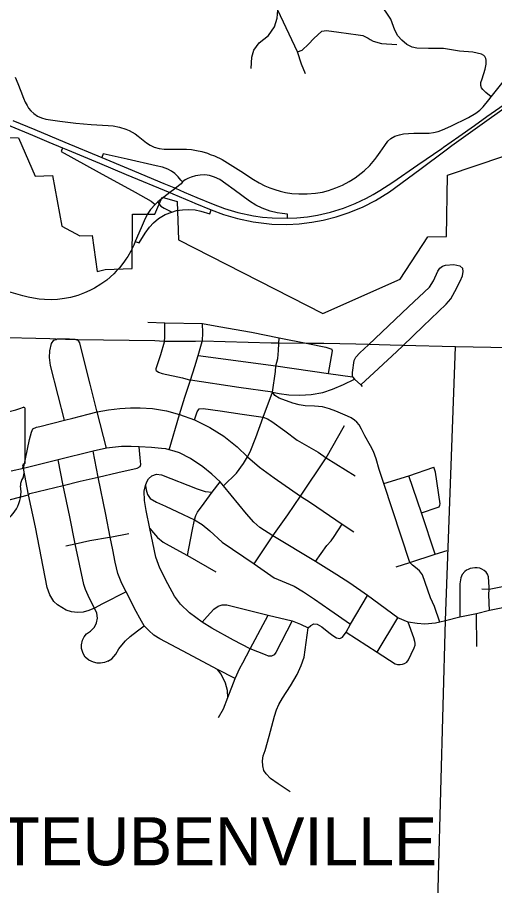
# Model space of a CAD drawing. Extents: x 2402298 to 2498138, y 789485 to 950881.
# Drawn here: x 2482051 to 2487007, y 865555 to 874577 of the extents above; entities that cross this region are included whole.
import ezdxf

# ---------------------------------------------------------------- set-up
doc = ezdxf.new("R2010")
doc.units = 0
for name, color, linetype in [('GM_X_City_Street', 7, 'Continuous'), ('GM_X_Corporation', 7, 'Continuous'), ('GM_X_Corporation_Text', 7, 'Continuous'), ('GM_X_County_Road', 7, 'Continuous'), ('GM_X_Interchange_Ramps', 7, 'Continuous'), ('GM_X_State_Route', 7, 'Continuous'), ('GM_X_State_Shield', 7, 'Continuous'), ('GM_X_Township', 7, 'Continuous'), ('GM_X_Township_Road', 7, 'Continuous'), ('GM_X_US_Route', 7, 'Continuous')]:
    doc.layers.add(name, color=color, linetype=linetype)

msp = doc.modelspace()

# ---------------------------------------------------------------- linework, layer by layer
at = {"layer": 'GM_X_City_Street'}
for p, q in [((2485259, 870000.6), (2485448.7, 870337.6)), ((2485785.7, 867979.3), (2486002.2, 868338)), ((2486821.1, 868038.8), (2486820, 868379.3))]:
    msp.add_line(p, q, dxfattribs=at)
for points in [[(2485529.5, 870840.6), (2485532.2, 870887.3), (2485548.1, 871011.7), (2485564.1, 871047.4), (2485608.8, 871091.4), (2485695.9, 871174), (2486111.1, 871567.8), (2486331.8, 871773.4), (2486373.6, 871839.4), (2486417.6, 871938), (2486437.3, 871972.2), (2486465.4, 871990), (2486498, 872000.2), (2486583.7, 872007.1), (2486647.5, 871994.9)], [(2485619.1, 870757.2), (2485801.5, 870928.6), (2485990.1, 871105), (2486052.9, 871165.3), (2486265.5, 871369), (2486503.7, 871596.6), (2486552.2, 871650.5), (2486594.7, 871728.7), (2486647.8, 871837.1), (2486672.9, 871892.5), (2486682, 871937.3), (2486677.4, 871968.4), (2486647.5, 871994.9)], [(2483406.8, 871408.5), (2483583.9, 871402.8), (2483973.6, 871397)], [(2483490.8, 870908.7), (2483492.5, 870926.9), (2483539.3, 871074.1), (2483577.9, 871205.5), (2483583.2, 871256.4), (2483583.9, 871402.8)], [(2483628.1, 870081.7), (2483736.2, 870449.4), (2483791.5, 870630.9), (2483849.8, 870805.7), (2483892.5, 870949.3), (2483929.2, 871064.9), (2483970.6, 871209.8), (2483972.4, 871216.1), (2483975.4, 871300.2), (2483973.6, 871397)], [(2483973.6, 871397), (2484143.6, 871365.7), (2484483.7, 871305.6), (2484769.1, 871246.2), (2485068.2, 871186.5), (2485254, 871149.4), (2485315.3, 871127.8)], [(2482541.1, 870391.7), (2482473.8, 870646.5), (2482395.7, 870957.8), (2482383.7, 871043.1), (2482387.9, 871112.8), (2482406.5, 871189.1), (2482430.6, 871222.7), (2482452.7, 871231), (2482466, 871235.9), (2482592.4, 871236.4), (2482648.7, 871232.9), (2482678.7, 871224), (2482682.9, 871222.7)], [(2482876.3, 870488.8), (2482806.7, 870766.1), (2482748.4, 870996.2), (2482698.6, 871193.9), (2482682.9, 871222.7)], [(2484190.9, 869709.4), (2484326.3, 869839.6), (2484400.3, 869940.5), (2484442.2, 870011.4), (2484469.3, 870062.4), (2484528.4, 870213), (2484603.9, 870422.9), (2484698.9, 870683.2), (2484731.9, 870897.1), (2484734.8, 870954.2), (2484755.9, 871030.4), (2484761.9, 871116.4), (2484765.9, 871188.9), (2484769.1, 871246.2)], [(2485281.1, 870876.7), (2485322.4, 871110.7), (2485315.3, 871127.8)], [(2483929.2, 871064.9), (2484734.8, 870954.2), (2485281.1, 870876.7), (2485529.5, 870840.6), (2485552.8, 870818.8), (2485619.1, 870757.2), (2485633.1, 870742.4)], [(2483490.8, 870908.7), (2483517.5, 870890.7), (2483554.5, 870877.6), (2483765.4, 870832.1), (2483849.8, 870805.7)], [(2486438.9, 868293.3), (2486382.7, 868453.8), (2486342.8, 868547.1), (2486259.5, 868783.4), (2486225.3, 868827.1), (2486186.6, 868860.1), (2486154.1, 868886), (2486128.1, 868911.3), (2485855.8, 869733.3), (2485807.2, 869879), (2485776.9, 869989.8), (2485750.3, 870064.9), (2485719.6, 870123.3), (2485658.5, 870227.2), (2485625.1, 870299.3), (2485600.5, 870344.4), (2485577, 870372.1), (2485551.5, 870393), (2485518.2, 870414.2), (2485479.5, 870432.8), (2485357.7, 870483.7), (2485290.9, 870508.7), (2485220.8, 870528.4), (2485137.3, 870536.8), (2485038.7, 870539.8), (2484977.2, 870550.4), (2484911.6, 870569), (2484770.5, 870619.1), (2484723.5, 870648.3), (2484698.9, 870683.2), (2484351.9, 870731.6), (2483849.8, 870805.7)], [(2484698.9, 870683.2), (2484771.2, 870668), (2484869.5, 870654.4), (2484985.6, 870652.1), (2485100.5, 870659.3), (2485222.7, 870679), (2485324.3, 870714.3), (2485438.5, 870762.5), (2485552.8, 870818.8)], [(2482213.1, 870300.4), (2482248.5, 870317.2), (2482284.6, 870325.7), (2482541.1, 870391.7), (2482626.6, 870411.5), (2482787.5, 870454.2), (2482878.8, 870478.9), (2482999, 870499.3), (2483115, 870513.7), (2483225.5, 870520.3), (2483326.5, 870520.3), (2483453.8, 870511.3), (2483600.4, 870487.9), (2483736.2, 870449.4), (2483891.9, 870395.4), (2484049.3, 870316.6), (2484196.5, 870223.5), (2484332.3, 870114.8), (2484442.2, 870011.4), (2484567.2, 869902.6), (2484717.4, 869793.9), (2484990.3, 869603.1), (2485093.6, 869534.3), (2485425.2, 869309.6), (2485546, 869230.3)], [(2482978, 870099.7), (2482878.8, 870478.9), (2482876.3, 870488.8)], [(2483891.9, 870395.4), (2483918.9, 870478.3), (2483939.3, 870508.3), (2483981.4, 870512.5), (2484158, 870487.3), (2484387, 870454.8), (2484603.9, 870422.9), (2484649.5, 870405.4), (2484695.2, 870377.1), (2484829.5, 870279.3), (2484956.5, 870185.2), (2485174.9, 870060), (2485259, 870000.6), (2485560.5, 869811.4)], [(2482114.5, 869887.6), (2482176.4, 870189.9), (2482199.2, 870267.4), (2482213.1, 870300.4)], [(2481885.7, 869543.8), (2482168.3, 869613.9), (2482182, 869631), (2482527.6, 869711.8), (2482704.7, 869756.9), (2482889.8, 869799.8), (2483093.2, 869847.2), (2483295, 869894.3), (2483324.9, 869909.8), (2483332.1, 869930.7), (2483326.1, 870000.9), (2483317.4, 870114.8)], [(2484314.5, 867708.8), (2484130.5, 867802.1), (2483825.2, 867965.2), (2483532, 868120.4), (2483469, 868159.1), (2483416.6, 868205.4), (2483368.8, 868255.4), (2483339.6, 868302.1), (2483268.7, 868434.5), (2483229.3, 868513.5), (2483181.5, 868609.1), (2483136, 868695.2), (2483095, 868798.7), (2483067.7, 868916), (2483041.6, 869045.3), (2483014.6, 869176.9), (2482968.3, 869411.7), (2482889.8, 869799.8), (2482838.2, 870068.2)], [(2482991, 867886.7), (2482956.9, 867875), (2482915.5, 867867), (2482879.5, 867868.1), (2482840.8, 867875.3), (2482791.6, 867898), (2482756.2, 867930.3), (2482733.4, 867967.5), (2482718.3, 868018.3), (2482716.8, 868057.4), (2482726.2, 868104.8), (2482745.5, 868138.9), (2482769.5, 868170.1), (2482811.2, 868200), (2482851.8, 868239.5), (2482873.4, 868286.2), (2482881.8, 868333.2), (2482874.9, 868384.4), (2482851.1, 868439.5), (2482798.9, 868539.2), (2482759.6, 868632.5), (2482741.2, 868685.6), (2482650.2, 869105.1), (2482594.8, 869387.4), (2482527.6, 869711.8), (2482475, 869978.4)], [(2484510.8, 868899.9), (2484704.7, 869189.9), (2484858.7, 869407.5), (2484990.3, 869603.1), (2485259, 870000.6)], [(2483181.5, 868609.1), (2482934.6, 868483.1), (2482851.1, 868439.5), (2482794.6, 868413.3), (2482734.7, 868396.6), (2482677, 868392.1), (2482613.7, 868398.5), (2482556.4, 868417.9), (2482511.2, 868443.3), (2482468.4, 868473.3), (2482431.2, 868508.9), (2482389.5, 868575.7), (2482361.8, 868652.3), (2482239.6, 869279), (2482168.3, 869613.9), (2482114.5, 869887.6)], [(2485855.8, 869733.3), (2486116.4, 869814.1), (2486375.5, 869902.5)], [(2486248.4, 869427.5), (2486410.2, 869483), (2486429.7, 869491.7), (2486437.3, 869507.6), (2486440.3, 869522), (2486391.8, 869852.8), (2486375.5, 869902.5)], [(2484904.7, 868304.9), (2484734.8, 867978.9), (2484716.2, 867952.7), (2484691.6, 867938.7), (2484660.5, 867940.2), (2484627.5, 867952.7), (2484469.7, 868016.8), (2484296.7, 868104.8), (2484070.2, 868229.3), (2483970.8, 868291.8), (2483837.3, 868389.7), (2483746.3, 868478.5), (2483681.8, 868564.2), (2483613.5, 868692.4), (2483530.8, 868854.8), (2483487.6, 868967.1), (2483427.6, 869267.5), (2483388.9, 869451.9), (2483370, 869558.1), (2483368.5, 869654.4), (2483382.5, 869713.4), (2483395, 869750), (2483413.2, 869782.6), (2483447.4, 869812.2), (2483494.4, 869828.9), (2483546.7, 869825.1), (2483919.8, 869679.5), (2484002.9, 869649.5), (2484074.2, 869643.1)], [(2486389.9, 869000.5), (2486248.4, 869427.5), (2486116.4, 869814.1)], [(2483382.5, 869713.4), (2483386.9, 869669.2), (2483401.3, 869620.7), (2483431.6, 869576.7), (2483495.3, 869538.7), (2483589.4, 869497), (2483773.8, 869409.8), (2483891, 869354.4), (2483971, 869308.9), (2484048.4, 869242.1), (2484178.9, 869124.5), (2484510.8, 868899.9), (2484718.7, 868754.6), (2484923.9, 868667.8), (2485021.8, 868608.6), (2485136, 868530.5), (2485296.1, 868421.6), (2485511, 868273.1)], [(2483816.6, 868986.8), (2483867.5, 869239.1), (2483891, 869354.4), (2483902.8, 869399.5), (2483921, 869435.9), (2483990, 869530), (2484074.2, 869643.1), (2484156.4, 869750.3)], [(2485145.7, 868922.7), (2485263, 869089.1), (2485309.3, 869137.2), (2485339.9, 869181), (2485425.2, 869309.6)], [(2483009.5, 869176.1), (2483014.6, 869176.9), (2483209.1, 869215.5)], [(2483427.6, 869267.5), (2483463.5, 869220.5), (2483505.2, 869173.8), (2483564.3, 869125.5), (2483696.8, 869051.3), (2483816.6, 868986.8), (2484111.8, 868815)], [(2482553.6, 869085.4), (2482650.2, 869105.1), (2482802.5, 869141.6), (2483009.5, 869176.1)], [(2485985.5, 868866.9), (2486128.1, 868911.3), (2486389.9, 869000.5), (2486512.8, 869037.6)], [(2486954.3, 868412.2), (2486947.7, 868577.6), (2486951.8, 868634.9), (2486949.6, 868656.4), (2486944.8, 868762.3), (2486933.9, 868790.7), (2486918.5, 868812.3), (2486898.2, 868830.8), (2486874.9, 868844.3), (2486852, 868852), (2486826.8, 868855.4), (2486800.8, 868857), (2486776.7, 868855.1), (2486754.2, 868850.3), (2486732, 868841.4), (2486714.4, 868832.4), (2486696, 868818.3), (2486671.1, 868787.8), (2486657.4, 868751.6), (2486647.1, 868689.9), (2486646.3, 868607.7), (2486647.1, 868342.8)], [(2486873.6, 868639.6), (2486951.8, 868634.9), (2487070.9, 868659.1), (2487158.5, 868673.5), (2487182.2, 868670.8), (2487201.3, 868661), (2487233.3, 868644.6), (2487284.5, 868686.2), (2487352.7, 868691.4), (2487425.8, 868692.8), (2487546.5, 868687.8), (2487694.7, 868691)], [(2483970.8, 868291.8), (2484021.9, 868350.6), (2484090.1, 868426.5), (2484134.9, 868457.6), (2484176.6, 868472), (2484224.8, 868471.7), (2484268.4, 868462.9), (2484654.3, 868366.9), (2484904.7, 868304.9), (2484989.6, 868271.4), (2485071.9, 868234.2), (2485097.3, 868258.1), (2485129.2, 868274), (2485163.7, 868271), (2485212.6, 868243.3), (2485285.4, 868185.6), (2485325.3, 868153.4), (2485365.5, 868130.3), (2485398.1, 868122.7), (2485427.7, 868136.3), (2485464.1, 868188.7), (2485511, 868273.1), (2485687.7, 868569.1)], [(2484138.1, 867302.9), (2484192, 867390.9), (2484236.8, 867511.5), (2484314.5, 867708.8), (2484362.3, 867814.6), (2484391.5, 867868.5), (2484469.7, 868016.8), (2484654.3, 868366.9)], [(2482991, 867886.7), (2483032, 867911.8), (2483074.1, 867959.2), (2483106.3, 868013.8), (2483134.8, 868054.4), (2483173.1, 868099.5), (2483221.3, 868142), (2483299.4, 868203.1), (2483368.8, 868255.4)], [(2484884.5, 866531.2), (2484757.8, 866611.6), (2484680.2, 866669.7), (2484634, 866715.4), (2484612.1, 866751.9), (2484599.6, 866798.2), (2484596.9, 866850.9), (2484604.2, 866903.3), (2484623.1, 866958.7), (2484665.2, 867109.3), (2484720.6, 867315.6), (2484742.6, 867382.4), (2484767.6, 867438.5), (2484804.1, 867504.5), (2484886.8, 867629.7), (2484955.8, 867748.1), (2484999, 867842.1), (2485028.6, 867929.4), (2485071.9, 868234.2)], [(2485464.1, 868188.7), (2485785.7, 867979.3), (2485974, 867858.2), (2485999.3, 867852.4), (2486027, 867852.4), (2486051.7, 867854.7), (2486072.8, 867861.8), (2486095.4, 867878.7), (2486113.9, 867902.6), (2486141.6, 867958.8), (2486171.1, 868025.3), (2486180.4, 868054.9), (2486181.6, 868073.3), (2486179, 868091.5), (2486169.2, 868130.6), (2486110.6, 868293.5)], [(2484236.8, 867511.5), (2484232.2, 867583.6), (2484214, 867660.2), (2484167, 867752.8), (2484130.5, 867802.1)]]:
    msp.add_lwpolyline(points, dxfattribs=at)
at = {"layer": 'GM_X_Corporation'}
msp.add_lwpolyline([(2481850.4, 873329.2), (2482062.8, 873325.6), (2482236.9, 872927.3), (2482417, 872932.4), (2482514.1, 872406.7), (2482698.4, 872305.7), (2482826.4, 872308.7), (2482881.4, 871935.8), (2482962.3, 871956.1), (2483244.6, 871968.3), (2483248.1, 872532.1), (2483478.3, 872533.2), (2483555.5, 872706.8), (2483709.4, 872664.7), (2483723.4, 872264.1), (2485221.9, 871501.1), (2486026.8, 871856), (2486313.6, 872296.7), (2486507.7, 872300.4), (2486516.2, 872938.6), (2487101.2, 873134.4)], dxfattribs=at)
at = {"layer": 'GM_X_County_Road'}
for points in [[(2486945.2, 873718.4), (2486970.6, 873750.8), (2487138.8, 873958.9), (2487221.9, 874062.1), (2487290, 874134.4), (2487363.8, 874197.6), (2487430.4, 874242), (2487518.9, 874294), (2487618.2, 874341.2), (2487707.3, 874378.9), (2487735.3, 874390.7)], [(2482027.7, 873955), (2482056.1, 873887.9), (2482086.2, 873808.1), (2482114.1, 873735.7), (2482132.3, 873694.2), (2482151.2, 873659.3), (2482168.1, 873633.7), (2482190.8, 873606), (2482223.6, 873576.4), (2482258.9, 873551.5), (2482302.6, 873532.4), (2482345.7, 873519.6), (2482490.6, 873498.3), (2482656.9, 873477.7), (2482737.2, 873469.4), (2482818.2, 873463.9), (2482935.2, 873457.9), (2482994, 873454.3), (2483046.3, 873447.9), (2483111.8, 873435.4), (2483176, 873415.6), (2483210.9, 873401), (2483242.4, 873384.3), (2483273.5, 873365.2), (2483304.1, 873341.8), (2483391.5, 873273.5), (2483429.3, 873249.8), (2483471.3, 873229.5), (2483524.3, 873214.5), (2483574.7, 873207.5), (2483678.9, 873208.5), (2483808.1, 873207.5), (2483860.2, 873202.3), (2483910.4, 873194.2), (2483965.8, 873181.5), (2484024.1, 873164.3), (2484053.7, 873153)], [(2485782.8, 873126.3), (2485818.2, 873174.6), (2485866, 873246.5), (2485898.5, 873290.4), (2485928.3, 873317.9), (2485971.3, 873341.6), (2486017.7, 873355.6), (2486060.4, 873365), (2486114, 873370.9), (2486168.9, 873373.3), (2486275.4, 873372.4), (2486326.8, 873373.8), (2486373.6, 873380.5), (2486422.4, 873392), (2486467.5, 873408), (2486553.8, 873446.4), (2486734.6, 873536.7), (2486813, 873581.4), (2486852.4, 873611.3), (2486888, 873645.7), (2486945.2, 873718.4)], [(2484053.7, 873153), (2484098.2, 873136.1), (2484177, 873098.1), (2484260.6, 873047.5), (2484370.3, 872977), (2484504.8, 872892), (2484561.1, 872858.3), (2484621.6, 872826.7), (2484671.5, 872805.5), (2484724.5, 872786.6), (2484780.2, 872770.4), (2484836.1, 872758.2), (2484900.8, 872747.4), (2484972.3, 872741.9), (2485061.4, 872741.5), (2485147.4, 872749.3), (2485219.3, 872762), (2485281.9, 872778), (2485358.1, 872803.6), (2485427.1, 872833.4), (2485496.4, 872869.7), (2485559.7, 872910.3), (2485653.1, 872983.2), (2485710.7, 873038.6), (2485763.5, 873100), (2485782.8, 873126.3)], [(2483765.5, 872868.4), (2483753.1, 872845.6), (2483694.6, 872800.4), (2483686, 872794)], [(2483686, 872794), (2483634.4, 872755.5), (2483511, 872659.9), (2483480.7, 872632.7), (2483433.2, 872579.2), (2483404.8, 872537.4), (2483376.6, 872485.8), (2483335.5, 872388.1), (2483276, 872249.3), (2483259.5, 872209.6), (2483229.2, 872146.8), (2483196.7, 872091.1), (2483178.7, 872064.4)], [(2483178.7, 872064.4), (2483157.8, 872033.3), (2483110.2, 871973.3), (2483077.8, 871938.5)], [(2483077.8, 871938.5), (2483052.6, 871911.5), (2482979.5, 871847.7), (2482917.4, 871803.3), (2482852.9, 871763.6), (2482804.9, 871738.5), (2482749.2, 871713.2), (2482680.7, 871688.3), (2482601.6, 871666.6), (2482540.2, 871654.4), (2482469.5, 871646.1), (2482402.6, 871643), (2482333.6, 871644.1), (2482278.4, 871648.4), (2482218.2, 871657.8), (2482162.3, 871668.8), (2482109, 871683.6), (2481766, 871778.9)]]:
    msp.add_lwpolyline(points, dxfattribs=at)
at = {"layer": 'GM_X_Interchange_Ramps'}
msp.add_line((2483511, 872659.9), (2483522.2, 872634.7), dxfattribs=at)
for points in [[(2482521.5, 873220.6), (2482506, 873182), (2482637.6, 873109.3), (2482901.4, 872964.9), (2483275.6, 872760.5), (2483440.1, 872666.6), (2483480.7, 872632.7)], [(2483765.5, 872868.4), (2483750.2, 872885.1), (2483719.9, 872920.9), (2483685.6, 872953.9), (2483650.2, 872978.8), (2483612.4, 872999.2), (2483559.4, 873018.7), (2483492.9, 873034.8), (2483189.8, 873103.2), (2483003.7, 873144.7), (2482943.1, 873159.4), (2482927.6, 873120)], [(2484854.6, 872489.6), (2484855.7, 872532.1), (2484801, 872537.1), (2484747.8, 872546.1), (2484677.6, 872562.7), (2484592.7, 872593.6), (2484526.1, 872625.7), (2484460.5, 872666), (2484301, 872783.7), (2484214.2, 872848.3), (2484153.8, 872890.5), (2484099.7, 872917.7), (2484044.9, 872933.7), (2483998.7, 872939.2), (2483950.5, 872938.4), (2483902.3, 872930.7), (2483855.6, 872916.4), (2483822.4, 872901.2), (2483794, 872887), (2483765.5, 872868.4)], [(2483276, 872249.3), (2483316.3, 872232.8), (2483377.4, 872333.2), (2483421.9, 872395.8), (2483463.4, 872440.7), (2483517.4, 872485.1), (2483584.8, 872526.7), (2483653.6, 872553.4)], [(2483522.2, 872634.7), (2483542.3, 872614.6), (2483575.2, 872594.1), (2483636.9, 872562.5), (2483653.6, 872553.4)], [(2483653.6, 872553.4), (2483704.7, 872568.7), (2483767.3, 872578.3), (2483828, 872580.7), (2483897.3, 872575.4), (2483955.5, 872563), (2484051.1, 872534.3), (2484064.4, 872575.8)]]:
    msp.add_lwpolyline(points, dxfattribs=at)
at = {"layer": 'GM_X_State_Route'}
msp.add_lwpolyline([(2487179.2, 868459.2), (2486954.3, 868412.2), (2486820, 868379.3), (2486647.1, 868342.8), (2486497.3, 868307.2), (2486438.9, 868293.3), (2486391.4, 868282), (2486282.9, 868271.7), (2486203.2, 868277.4), (2486110.6, 868293.5), (2486002.2, 868338), (2485687.7, 868569.1), (2485502.2, 868698.9), (2485366.8, 868786.1), (2485145.7, 868922.7), (2484704.7, 869189.9), (2484569.4, 869274.7), (2484505.3, 869332.4), (2484430.6, 869417.3), (2484190.9, 869709.4), (2484156.4, 869750.3), (2484071.7, 869829.3), (2483977.8, 869908.1), (2483847.4, 869993.4), (2483733.8, 870050.5), (2483679.9, 870069), (2483628.1, 870081.7), (2483593, 870091.8), (2483547.6, 870098.5), (2483444.7, 870108.9), (2483317.4, 870114.8), (2483233.4, 870119.1), (2483132.4, 870116.6), (2482978, 870099.7), (2482838.2, 870068.2), (2482475, 869978.4), (2482114.5, 869887.6), (2481987.7, 869860)], dxfattribs=at)
at = {"layer": 'GM_X_State_Shield'}
for p, q in [((2482133, 869954.4), (2482133, 870507.1)), ((2482132.9, 869954.5), (2482133, 869954.4))]:
    msp.add_line(p, q, dxfattribs=at)
for centre, radius, start, end in [((2481637.1, 871921.5), 1476.4, 275.84447, 288.90645), ((2482117.6, 870509.4), 15.5, 351.86209, 97.738), ((2482129.4, 869913.8), 24, 107.94398, 210.33697), ((2482116.5, 869952.3), 16.6, 289.60381, 7.73413), ((2481976.9, 869844), 144, 340.03296, 23.64957), ((2482188.5, 869723.1), 104.8, 136.8065, 186.92959), ((2481719.8, 869652.8), 369.3, 292.30889, 8.98584)]:
    msp.add_arc(centre, radius, start, end, dxfattribs=at)
at = {"layer": 'GM_X_Township'}
for points in [[(2489542.6, 871097.4), (2486600.6, 871154.8), (2486051.9, 871168.2), (2485920.7, 871171.3), (2485694.9, 871176.8), (2485565.5, 871180), (2485234.6, 871188), (2485067.2, 871189.4), (2484764.9, 871191.7), (2484686.1, 871192.4), (2483969.5, 871212.7), (2483899.7, 871207.7), (2483576.8, 871208.4), (2483478.4, 871215.9), (2482677.6, 871226.9), (2482550, 871228.6), (2482451.7, 871233.9), (2482386.8, 871237.3), (2480043.8, 871291.1)], [(2485904.9, 840570.6), (2485987.5, 845862.2), (2486060.7, 849211.7), (2486136.9, 855690.8), (2486146.9, 856025.1), (2486178.7, 857085.2), (2486182.5, 857210.8), (2486195.1, 857630.5), (2486196.1, 857665.1), (2486213.6, 858070.3), (2486282.9, 860742.1), (2486351.3, 862991.1), (2486496.3, 868310.1), (2486600.6, 871154.8)]]:
    msp.add_lwpolyline(points, dxfattribs=at)
at = {"layer": 'GM_X_Township_Road'}
for points in [[(2486970.6, 873750.8), (2486916.3, 873794.4), (2486883.2, 873826.1), (2486869.7, 873846), (2486863.5, 873870), (2486865.5, 873899.8), (2486877.5, 873939.2), (2486908.5, 874040), (2486918.5, 874089), (2486918.8, 874130.6), (2486914.8, 874150.3), (2486905.6, 874168.4), (2486893.3, 874181.7), (2486872.3, 874192.6), (2486781.8, 874213.3), (2486642.2, 874226.3), (2486476.8, 874254.7), (2486319.1, 874252.1), (2486199.8, 874255.4), (2486149.3, 874265.3), (2486095.1, 874294.7), (2486042.2, 874339.5), (2486002.8, 874386.2), (2485969.8, 874443), (2485928.5, 874559.3), (2485814.7, 874727.5)], [(2484479.8, 874046.4), (2484485.6, 874162.2), (2484506.4, 874235.1), (2484562.3, 874311.2), (2484657.8, 874387.9), (2484722.9, 874477.5), (2484750.4, 874567.3), (2484756.2, 874649.7)], [(2485044.1, 873990), (2485002.1, 874091.3), (2484961.6, 874217.1), (2484756.2, 874649.7)], [(2484961.6, 874217.1), (2485009.3, 874237.4), (2485075.9, 874296.7), (2485130.9, 874356), (2485211.2, 874434.8), (2485261.1, 874441.4), (2485388.4, 874424), (2485589.5, 874395.1), (2485638.7, 874389.3), (2485692.2, 874361.8), (2485715.9, 874347.4)], [(2485715.9, 874347.4), (2485744.3, 874330), (2485831.2, 874305.4), (2485990.3, 874295.3)]]:
    msp.add_lwpolyline(points, dxfattribs=at)
at = {"layer": 'GM_X_US_Route'}
for p, q in [((2482377.5, 873281), (2482521.5, 873220.6)), ((2482521.5, 873220.6), (2482571.2, 873200)), ((2483664.2, 872742.9), (2483863.1, 872659.1))]:
    msp.add_line(p, q, dxfattribs=at)
for points in [[(2486457.4, 873214.9), (2486474.8, 873226.8), (2486633.7, 873337.3), (2486796.7, 873453.6), (2486926.8, 873546.8), (2487060.1, 873641.3), (2487286.3, 873802.8), (2487486.7, 873945.6), (2487575.5, 874011.1), (2487671.2, 874075.7), (2487771.1, 874148.2), (2487851.2, 874192.3), (2487861.4, 874197.5)], [(2486563.7, 873244.4), (2486829.2, 873436.4), (2487154.1, 873667.1), (2487292.1, 873766.1)], [(2481798.4, 873524.6), (2481981.8, 873447.3), (2482209.6, 873351.4), (2482377.5, 873281)], [(2482005.1, 873505.8), (2482232.9, 873409.8), (2482544.9, 873279.1), (2482927.6, 873120), (2483201.9, 873004.7), (2483572.5, 872848.7), (2483694.6, 872800.4), (2483782.4, 872761), (2483913.5, 872706.1), (2484085.1, 872635.4), (2484203.3, 872591.2), (2484342.2, 872548.7), (2484504.8, 872514.6), (2484596.1, 872501.8), (2484697.9, 872492.8), (2484854.6, 872489.6), (2484952, 872494.1), (2485064.5, 872505.6), (2485168.3, 872522), (2485302.2, 872553), (2485438, 872595.3), (2485560.4, 872643), (2485675.7, 872697.5), (2485746.2, 872736), (2485815.1, 872776.7), (2485950, 872865.4), (2486209.5, 873044.8), (2486457.4, 873214.9)], [(2482571.2, 873200), (2482904.3, 873061.6), (2483181.3, 872945.1), (2483634.4, 872755.5), (2483664.2, 872742.9)], [(2484064.4, 872575.8), (2484190.8, 872527.7), (2484337.6, 872485), (2484500.2, 872451), (2484693.3, 872429.2), (2484850, 872426), (2484976.1, 872431.4), (2485108.3, 872446.9), (2485227.8, 872470), (2485362.3, 872504.1), (2485497.2, 872548.6), (2485640.3, 872608.6), (2485770.2, 872674.9), (2485917, 872765), (2486231.5, 872997.4), (2486503.8, 873201.1), (2486563.7, 873244.4)], [(2483863.1, 872659.1), (2483892.9, 872646.5), (2484064.4, 872575.8)]]:
    msp.add_lwpolyline(points, dxfattribs=at)

# ---------------------------------------------------------------- texts
at = {"layer": 'GM_X_Corporation_Text'}
msp.add_text('STEUBENVILLE', height=500, rotation=0.00001, dxfattribs=at).set_placement((2481429.4, 865766.3))

doc.saveas('drawing.dxf')
